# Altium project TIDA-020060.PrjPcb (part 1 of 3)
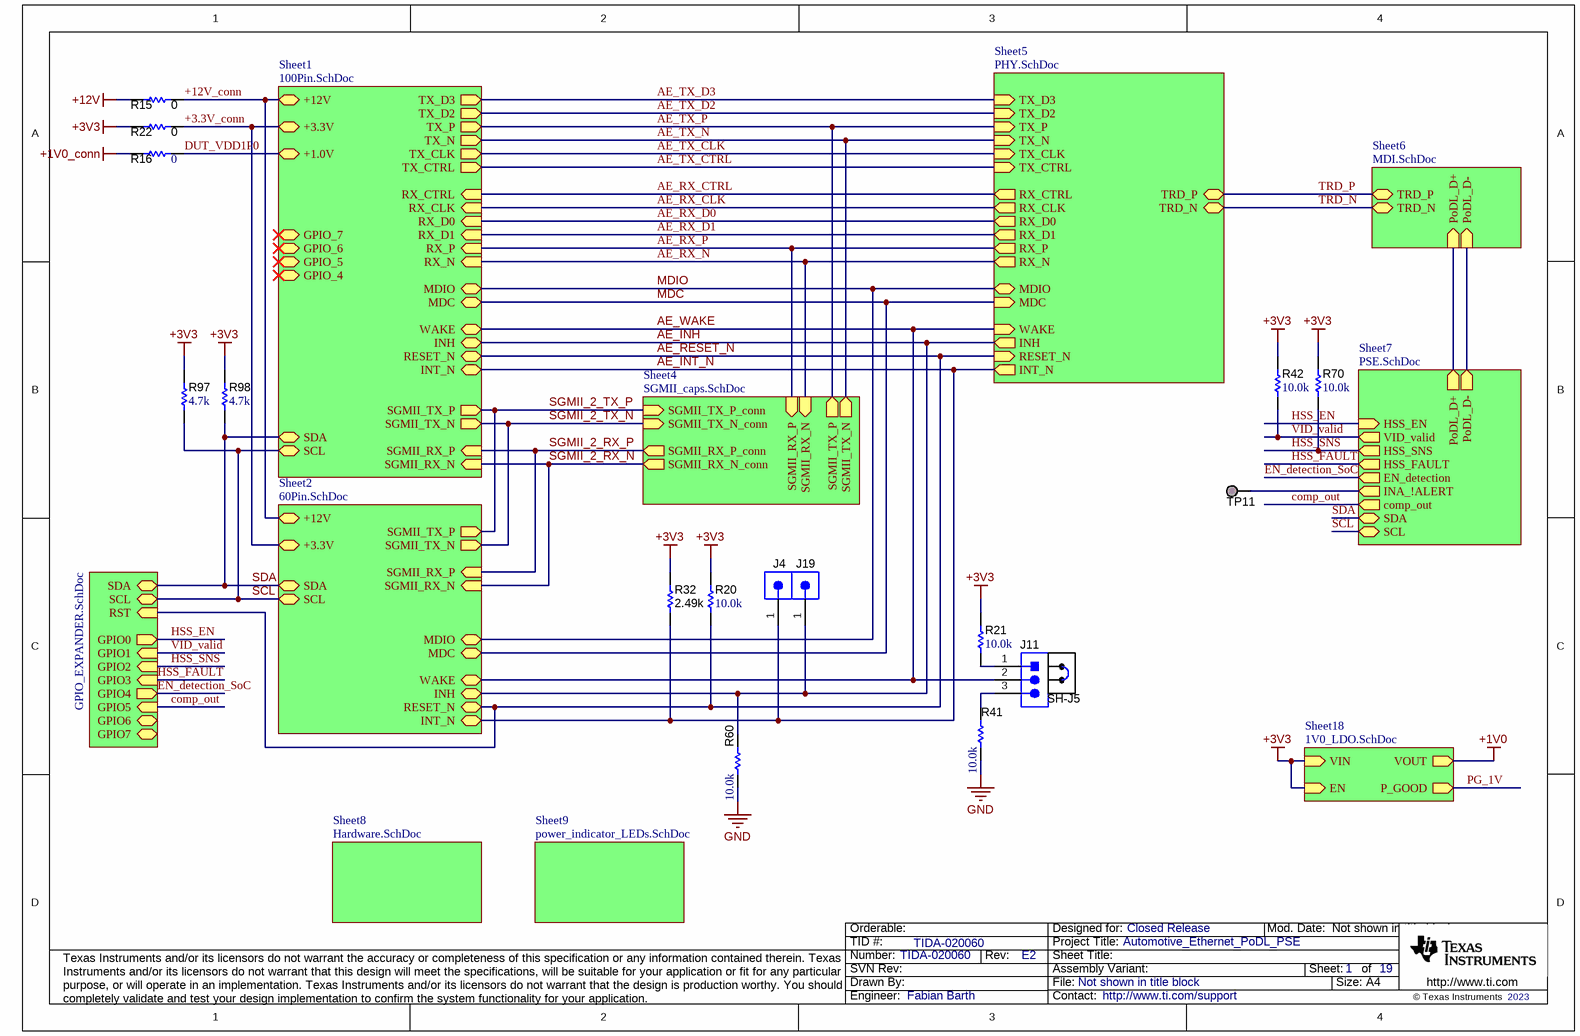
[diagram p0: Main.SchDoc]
CopyrightYear: 2023; PCB_Layout: Fabian Barth; PCB_Rev: E2; PRJ_Customer: Closed Release; PRJ_Engineer: Fabian Barth; PRJ_Number: TIDA-020060; PRJ_Title: Automotive_Ethernet_PoDL_PSE; SCH_Rev: E2; TechSupport: http://www.ti.com/support; TID: TIDA-020060
19 sheets, 281 parts. Net scope: hierarchical (ports join the sheet entries above them; power ports are global).
Board file: TIDA-020060.PcbDoc
Sheets:
  Main.SchDoc
    Sheet5 = PHY.SchDoc
      Sheet10 = Power_caps.SchDoc
      Sheet11 = PHY_LED.SchDoc
    Sheet6 = MDI.SchDoc
    Sheet8 = Hardware.SchDoc
    Sheet1 = 100Pin.SchDoc
    Sheet2 = 60Pin.SchDoc
      Sheet3 = Board_ID_EEPROM.SchDoc
    Sheet4 = SGMII_caps.SchDoc
    Sheet9 = power_indicator_LEDs.SchDoc
    Sheet18 = 1V0_LDO.SchDoc
    Sheet7 = PSE.SchDoc
      HSS = High_side_switch.SchDoc
      LM5158QRTERQ1 = PSE_BOOST.SchDoc
      Detections_sheet = Detection_PSE.SchDoc
      current_sense_sheet = INA237.SchDoc
    GPIO_expander = GPIO_EXPANDER.SchDoc
  Automotive_PoDL_PSE_Adapter_Hardware.SchDoc

## Sheet Main.SchDoc
size A4; Date: Not shown in title block; ApprovedBy: Not shown in title block; CheckedBy: Not shown in title block; Author: Not shown in title block; CompanyName: Not shown in title block; Engineer: Not shown in title block; Organization: Not shown in title block; Address1: Not shown in title block; Address2: Not shown in title block; Address3: Not shown in title block; Address4: Not shown in title block; DocumentNumber: 1; Revision: Use project parameter SCH_Rev; SheetNumber: 1; SheetTotal: 19; PageSetup: Record=PageOptions¦CenterHorizontal=True¦CenterVertical=True¦PrintScale=0.93¦XCorrection=1.00¦YCorrection=1.00¦PrintKind=0¦BorderSize=5000000¦LeftOffset=0¦BottomOffset=0¦Orientation=2¦PaperLength=1000¦PaperWidth=1000¦Scale=100¦PaperSource=15¦PrintQuality=600¦MediaType=1¦DitherType=10¦PaperKind=Letter¦PrintScaleMode=1

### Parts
J4  61300111121  [WURTH_61300111121]  (value not drawn)
J11  TSW-103-07-G-S  [TSW-103-07-G-S]  (value not drawn)
J19  61300111121  [WURTH_61300111121]  (value not drawn)
R15  ValueDisplayed: 0  [0603]  (hidden comment: RMCF0603ZT0R00)
R16  ValueDisplayed: 0  [0402]  (hidden comment: RK73Z1ETTP)
R20  ValueDisplayed: 10.0k  [0402]  (hidden comment: RMCF0402FT10K0)
R21  ValueDisplayed: 10.0k  [0402]  (hidden comment: RMCF0402FT10K0)
R22  ValueDisplayed: 0  [0603]  (hidden comment: RMCF0603ZT0R00)
R32  ValueDisplayed: 2.49k  [0603]  (hidden comment: CRCW06032K49FKEA)
R41  ValueDisplayed: 10.0k  [0402]  (hidden comment: RMCF0402FT10K0)
R42  ValueDisplayed: 10.0k  [0603]  (hidden comment: RT0603DRE0710KL)
R60  ValueDisplayed: 10.0k  [0402]  (hidden comment: RMCF0402FT10K0)
R70  ValueDisplayed: 10.0k  [0402]  (hidden comment: RMCF0402FT10K0)
R97  ValueDisplayed: 4.7k  [0402S]  (hidden comment: CRCW04024K70JNED)
R98  ValueDisplayed: 4.7k  [0402S]  (hidden comment: CRCW04024K70JNED)
SH-J5  SPC02SYAN  [SPC02SYAN]  (value not drawn)
TP11  TP_SM_1MM  [TP_SM_1MM]  (value not drawn)  (no BOM)

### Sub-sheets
GPIO_expander = GPIO_EXPANDER.SchDoc: RST (in), SCL (bidir), SDA (bidir), GPIO0 (out), GPIO1 (in), GPIO2 (in), GPIO3 (in), GPIO4 (out), GPIO5 (in), GPIO6 (bidir), GPIO7 (bidir)
Sheet1 = 100Pin.SchDoc: +12V (bidir), +3.3V (bidir), +1.0V (bidir), SGMII_TX_P (out), SGMII_TX_N (out), SGMII_RX_P (in), SGMII_RX_N (in), INT_N (bidir), RESET_N (bidir), INH (bidir), WAKE (bidir), MDIO (bidir), MDC (bidir), TX_D3 (out), TX_D2 (out), TX_P (out), TX_N (out), TX_CLK (out), TX_CTRL (out), RX_CTRL (in), RX_CLK (in), RX_D0 (in), RX_D1 (in), RX_P (in), RX_N (in), SDA (bidir), SCL (bidir), GPIO_7 (bidir), GPIO_6 (bidir), GPIO_5 (bidir), GPIO_4 (bidir)
Sheet2 = 60Pin.SchDoc: +12V (bidir), +3.3V (bidir), SDA (bidir), SCL (bidir), WAKE (bidir), INH (bidir), RESET_N (bidir), MDIO (bidir), MDC (bidir), SGMII_RX_N (in), SGMII_RX_P (in), SGMII_TX_N (out), SGMII_TX_P (out), INT_N (bidir)
Sheet4 = SGMII_caps.SchDoc: SGMII_RX_P (in), SGMII_RX_N (in), SGMII_TX_P (out), SGMII_TX_N (out), SGMII_RX_P_conn (out), SGMII_RX_N_conn (out), SGMII_TX_P_conn (in), SGMII_TX_N_conn (in)
Sheet5 = PHY.SchDoc: TX_D3 (in), TX_D2 (in), TX_P (in), TX_N (in), TX_CLK (in), TX_CTRL (in), RX_CTRL (out), RX_CLK (out), RX_D0 (out), RX_D1 (out), RX_P (out), RX_N (out), MDIO (bidir), MDC (in), TRD_P (bidir), TRD_N (bidir), WAKE (in), RESET_N (in), INT_N (out), INH (out)
Sheet6 = MDI.SchDoc: TRD_P (bidir), TRD_N (bidir), PoDL_D+ (in), PoDL_D- (in)
Sheet7 = PSE.SchDoc: PoDL_D+ (out), PoDL_D- (out), HSS_EN (in), VID_valid (out), HSS_SNS (out), HSS_FAULT (out), EN_detection (out), INA_!ALERT (out), SDA (bidir), SCL (bidir), comp_out (out)
Sheet8 = Hardware.SchDoc: no entries
Sheet9 = power_indicator_LEDs.SchDoc: no entries
Sheet18 = 1V0_LDO.SchDoc: EN (in), VIN (in), P_GOOD (out), VOUT (out)

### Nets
+1V0_conn: R16.2
+3V3: R20.2 R21.2 R22.1 R32.1 R42.2 R70.2 R97.2 R98.2 ; sheet Sheet18/EN, sheet Sheet18/VIN
+12V: R15.1
GND: R41.2 R60.2
!ALERT: TP11.1 ; sheet Sheet7/INA_!ALERT
+3.3V_conn: R22.2 ; sheet Sheet1/+3.3V, sheet Sheet2/+3.3V
+12V_conn: R15.2 ; sheet Sheet1/+12V, sheet Sheet2/+12V
AE_INH: J19.1 R60.1 ; sheet Sheet5/INH, sheet Sheet1/INH, sheet Sheet2/INH
AE_INT_N: J4.1 R32.2 ; sheet Sheet5/INT_N, sheet Sheet1/INT_N, sheet Sheet2/INT_N
AE_RESET_N: R20.1 ; sheet Sheet5/RESET_N, sheet Sheet1/RESET_N, sheet Sheet2/RESET_N, sheet GPIO_expander/RST
AE_RX_CLK: sheet Sheet5/RX_CLK, sheet Sheet1/RX_CLK
AE_RX_CTRL: sheet Sheet5/RX_CTRL, sheet Sheet1/RX_CTRL
AE_RX_D0: sheet Sheet5/RX_D0, sheet Sheet1/RX_D0
AE_RX_D1: sheet Sheet5/RX_D1, sheet Sheet1/RX_D1
AE_RX_N: sheet Sheet5/RX_N, sheet Sheet1/RX_N, sheet Sheet4/SGMII_RX_N
AE_RX_P: sheet Sheet5/RX_P, sheet Sheet1/RX_P, sheet Sheet4/SGMII_RX_P
AE_TX_CLK: sheet Sheet5/TX_CLK, sheet Sheet1/TX_CLK
AE_TX_CTRL: sheet Sheet5/TX_CTRL, sheet Sheet1/TX_CTRL
AE_TX_D2: sheet Sheet5/TX_D2, sheet Sheet1/TX_D2
AE_TX_D3: sheet Sheet5/TX_D3, sheet Sheet1/TX_D3
AE_TX_N: sheet Sheet5/TX_N, sheet Sheet1/TX_N, sheet Sheet4/SGMII_TX_N
AE_TX_P: sheet Sheet5/TX_P, sheet Sheet1/TX_P, sheet Sheet4/SGMII_TX_P
AE_WAKE: J11.2 ; sheet Sheet5/WAKE, sheet Sheet1/WAKE, sheet Sheet2/WAKE
comp_out: sheet Sheet7/comp_out, sheet GPIO_expander/GPIO5
DUT_VDD1P0: R16.1 ; sheet Sheet1/+1.0V
EN_detection_SoC: sheet Sheet7/EN_detection, sheet GPIO_expander/GPIO4
HSS_EN: sheet Sheet7/HSS_EN, sheet GPIO_expander/GPIO0
HSS_FAULT: sheet Sheet7/HSS_FAULT, sheet GPIO_expander/GPIO3
HSS_SNS: R70.1 ; sheet Sheet7/HSS_SNS, sheet GPIO_expander/GPIO2
MDC: sheet Sheet5/MDC, sheet Sheet1/MDC, sheet Sheet2/MDC
MDIO: sheet Sheet5/MDIO, sheet Sheet1/MDIO, sheet Sheet2/MDIO
PoDL_D+: sheet Sheet6/PoDL_D+, sheet Sheet7/PoDL_D+
PoDL_D-: sheet Sheet6/PoDL_D-, sheet Sheet7/PoDL_D-
SCL: R97.1 ; sheet Sheet1/SCL, sheet Sheet2/SCL, sheet Sheet7/SCL, sheet GPIO_expander/SCL
SDA: R98.1 ; sheet Sheet1/SDA, sheet Sheet2/SDA, sheet Sheet7/SDA, sheet GPIO_expander/SDA
SGMII_2_RX_N: sheet Sheet1/SGMII_RX_N, sheet Sheet2/SGMII_RX_N, sheet Sheet4/SGMII_RX_N_conn
SGMII_2_RX_P: sheet Sheet1/SGMII_RX_P, sheet Sheet2/SGMII_RX_P, sheet Sheet4/SGMII_RX_P_conn
SGMII_2_TX_N: sheet Sheet1/SGMII_TX_N, sheet Sheet2/SGMII_TX_N, sheet Sheet4/SGMII_TX_N_conn
SGMII_2_TX_P: sheet Sheet1/SGMII_TX_P, sheet Sheet2/SGMII_TX_P, sheet Sheet4/SGMII_TX_P_conn
TRD_N: sheet Sheet5/TRD_N, sheet Sheet6/TRD_N
TRD_P: sheet Sheet5/TRD_P, sheet Sheet6/TRD_P
VID_valid: R42.1 ; sheet Sheet7/VID_valid, sheet GPIO_expander/GPIO1  [project net Q]
NetJ11_1: J11.1 R21.1
NetJ11_3: J11.3 R41.1

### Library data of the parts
J4 J19 = CMP-0054792-1: Header, 2.54 mm, 1x1, Gold, TH; Manufacturer: Wurth Elektronik; CNHeader: TRUE; CT: FALSE
J11 = CMP-0075407-2: Header, 100mil, 3x1, Gold, TH; Manufacturer: Samtec; Pitch_mm: 2.54; Cert_VDE: N; Gender: Male; Cert_CSA: Y; Voltage_V: 550V; Green_REACh: Passed; Current_A: 6.3A; Green_Lifecycle: Active; Row_Count: 1
R15 R22 = CMP-0023343-3: RES, 0, 1%, 0.1 W, AEC-Q200 Grade 0, 0603; Manufacturer: Stackpole Electronics Inc; Power_W: 100mW; TempCo: ppm/C; U/M: EA; Value: 0; SizeX_mm: 1.6; SizeY_mm: 0.8; SizeZ_mm: 1; Value2: 0.1W; SizeArea_mm2: 1.28; AEC Qualified: Y; AEC Category: Q200
R16 = CMP-0027007-2: RES, 0, 5%, 0.063 W, AEC-Q200 Grade 0, 0402; Manufacturer: KOA Speer; Power_W: 63mW; TempCo: ppm/C; Value_Code: 0000; Value: 0; EIA_Code: E24; SizeX_mm: 1; SizeY_mm: 0.5; SizeZ_mm: 0.6; Value2: 0.063W; AEC Qualified: Y; AEC Category: Q200; U/M: EA
R20 R21 R70 = CMP-0026754-1: RES, 10.0 k, 1%, 0.063 W, AEC-Q200 Grade 0, 0402; Manufacturer: Stackpole Electronics Inc; Power_W: 63mW; TempCo: 100 ppm/C; Value_Code: 10k0; U/M: EA; Value: 10.0k; EIA_Code: E96; Res_ohm: 10k; SizeX_mm: 1; SizeY_mm: 0.5; SizeZ_mm: 0.6; Value2: 0.063W; AEC Qualified: Y; VDC_V: 50V; AEC Grade: 0; AEC Category: Q200
R32 = CMP-0022277-4: RES, 2.49 k, 1%, 0.1 W, AEC-Q200 Grade 0, 0603; Manufacturer: Vishay-Dale; Power_W: 100mW; TempCo: 100 ppm/C; Value_Code: 2k49; Value: 2.49k; EIA_Code: E96; SizeX_mm: 1.6; SizeY_mm: 0.8; SizeZ_mm: 1; Value2: 0.1W; SizeArea_mm2: 1.28; AEC Qualified: Y; VDC_V: 75V; AEC Category: Q200; AEC Grade: 0
R41 R60 = CMP-0026754-1: RES, 10.0 k, 1%, 0.063 W, AEC-Q200 Grade 0, 0402; Manufacturer: Stackpole Electronics Inc; Power_W: 63mW; TempCo: 100 ppm/C; Value_Code: 10k0; Value: 10.0k; EIA_Code: E96; Res_ohm: 10k; SizeX_mm: 1; SizeY_mm: 0.5; SizeZ_mm: 0.6; Value2: 0.063W; AEC Qualified: Y; VDC_V: 50V; AEC Category: Q200; AEC Grade: 0; U/M: EA
R42 = CMP-0024586-3: RES, 10.0 k, 0.5%, 0.1 W, 0603; Manufacturer: Yageo America; Power_W: 100mW; TempCo: 50 ppm/C; Value_Code: 10k0; U/M: EA; Value: 10.0k; EIA_Code: E192; Res_ohm: 10k; SizeX_mm: 1.6; SizeY_mm: 0.8; SizeZ_mm: 1; Value2: 0.1W; SizeArea_mm2: 1.28; VDC_V: 75V; AEC Category: Q200
R97 R98 = CMP-0026938-5: RES, 4.7 k, 5%, 0.063 W, AEC-Q200 Grade 0, 0402; Manufacturer: Vishay-Dale; Power_W: 63mW; TempCo: 200 ppm/C; Value_Code: 4k70; Value: 4.7k; EIA_Code: E24; SizeX_mm: 1; SizeY_mm: 0.5; SizeZ_mm: 0.6; Value2: 0.063W; AEC Qualified: Y; VDC_V: 50V; AEC Grade: 0; AEC Category: Q200
SH-J5 = CMP-0003642-1: Shunt, 100mil, Flash Gold, Black; Manufacturer: Sullins Connector Solutions; Value: 1x2; Note: You can "mate" this to a header by matching the designator.  i.e. use SH-J3 for header J3
TP11 = CMP-0003825-1: 1mm Test Point, SMT; Manufacturer: Any

## Sheet PHY.SchDoc
size A4; Date: Not shown in title block; ApprovedBy: Not shown in title block; CheckedBy: Not shown in title block; Author: Not shown in title block; CompanyName: Not shown in title block; Engineer: Not shown in title block; Organization: Not shown in title block; Address1: Not shown in title block; Address2: Not shown in title block; Address3: Not shown in title block; Address4: Not shown in title block; DocumentNumber: 6; Revision: Use project parameter SCH_Rev; SheetNumber: 6; SheetTotal: 19; PageSetup: Record=PageOptions¦CenterHorizontal=True¦CenterVertical=True¦PrintScale=0.93¦XCorrection=1.00¦YCorrection=1.00¦PrintKind=0¦BorderSize=5000000¦LeftOffset=0¦BottomOffset=0¦Orientation=2¦PaperLength=1000¦PaperWidth=1000¦Scale=100¦PaperSource=15¦PrintQuality=600¦MediaType=1¦DitherType=10¦PaperKind=Letter¦PrintScaleMode=1
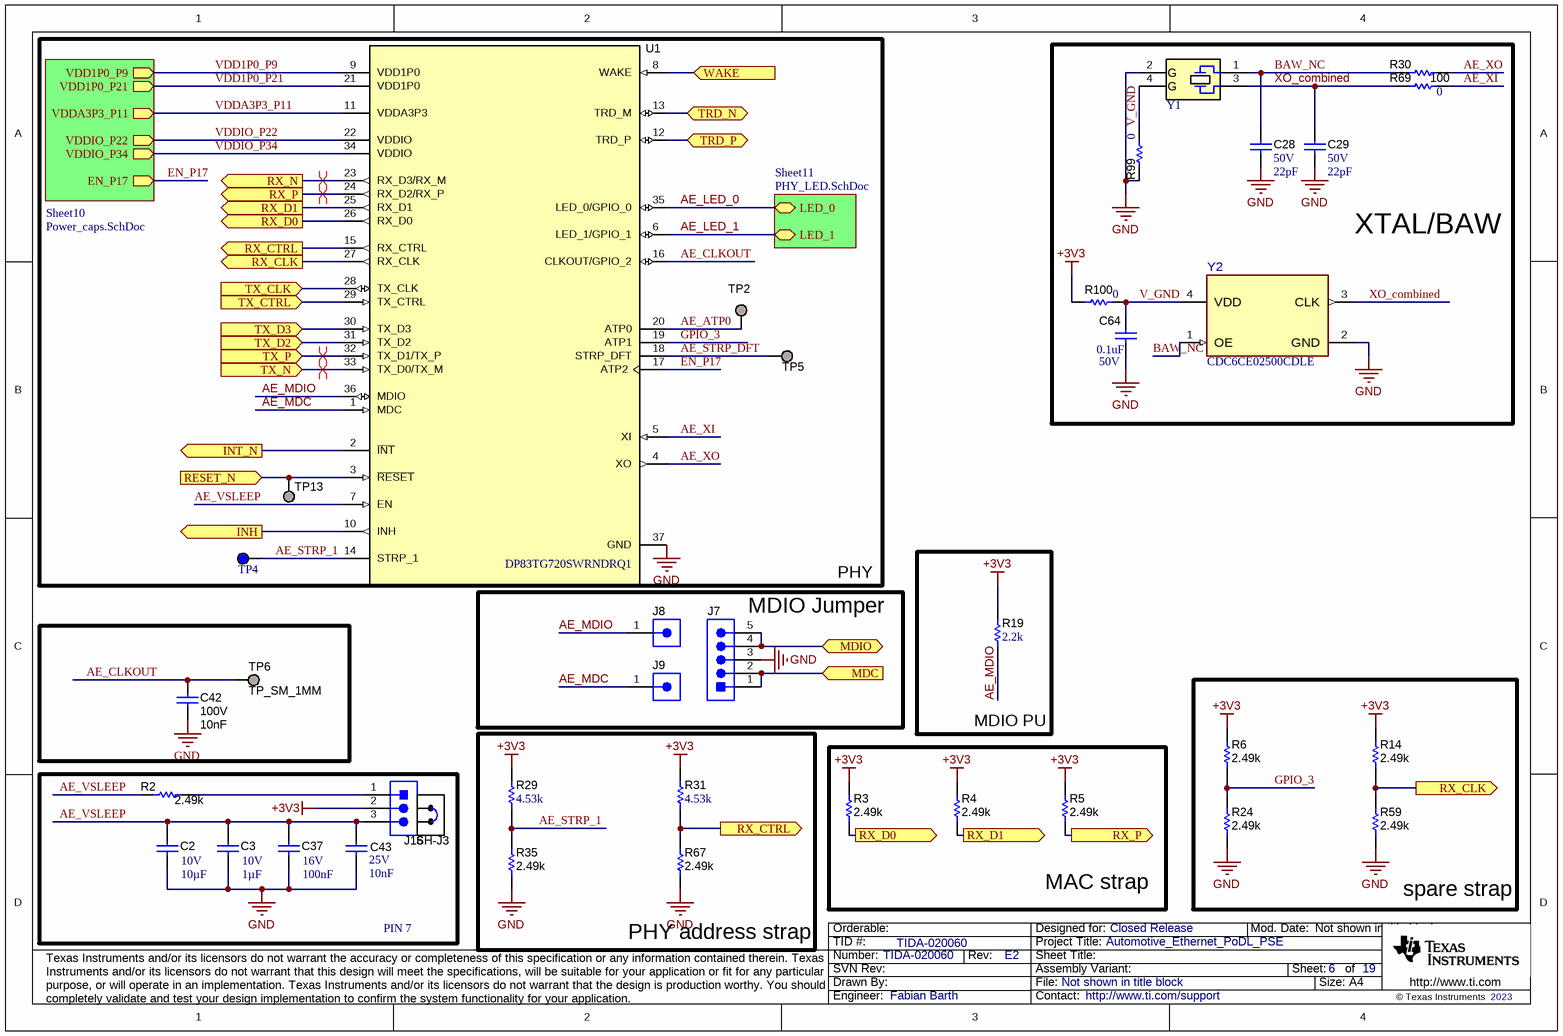
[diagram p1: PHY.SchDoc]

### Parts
C2  VDC_V: 10V  Cap_F: 10µF  [0402S]  (hidden comment: GRM155R61A106ME11D)
C3  Cap_F: 1µF  VDC_V: 10V  [0402S]  (hidden comment: GRT155C71A105KE13D)
C28  VDC_V: 50V  ValueDisplayed: 22pF  [0603]  (hidden comment: CGA3E2C0G1H220J080AA)
C29  VDC_V: 50V  ValueDisplayed: 22pF  [0603]  (hidden comment: CGA3E2C0G1H220J080AA)
C37  Cap_F: 100nF  VDC_V: 16V  [0402S]  (hidden comment: C0402C104K4RACAUTO)
C42  VDC_V: 100V  Cap_F: 10nF  [0603]  (hidden comment: GCM188R72A103KA37J)
C43  VDC_V: 25V  Cap_F: 10nF  [0402S]  (hidden comment: GRM155R71E103KA01D)
C64  ValueDisplayed: 0.1uF  VDC_V: 50V  [0402]  (hidden comment: C1005X5R1H104K050BB)
J7  TSW-105-07-G-S  [TSW-105-07-X-S]  (value not drawn)
J8  61300111121  [WURTH_61300111121]  (value not drawn)
J9  61300111121  [WURTH_61300111121]  (value not drawn)
J16  TSW-103-07-G-S  [TSW-103-07-X-S]  (value not drawn)
R2  ValueDisplayed: 2.49k  [0603]  (hidden comment: CRCW06032K49FKEA)
R3  ValueDisplayed: 2.49k  [0603]  (hidden comment: CRCW06032K49FKEA)
R4  ValueDisplayed: 2.49k  [0603]  (hidden comment: CRCW06032K49FKEA)
R5  ValueDisplayed: 2.49k  [0603]  (hidden comment: CRCW06032K49FKEA)
R6  ValueDisplayed: 2.49k  [0603]  (hidden comment: CRCW06032K49FKEA)
R14  ValueDisplayed: 2.49k  [0603]  (hidden comment: CRCW06032K49FKEA)
R19  ValueDisplayed: 2.2k  [0402]  (hidden comment: CRCW04022K20JNED)
R24  ValueDisplayed: 2.49k  [0603]  (hidden comment: CRCW06032K49FKEA)
R29  ValueDisplayed: 4.53k  [0603]  (hidden comment: CRCW06034K53FKEA)
R30  ValueDisplayed: 100  [0402]  (hidden comment: CRCW0402100RFKED)
R31  ValueDisplayed: 4.53k  [0603]  (hidden comment: CRCW06034K53FKEA)
R35  ValueDisplayed: 2.49k  [0603]  (hidden comment: CRCW06032K49FKEA)
R59  ValueDisplayed: 2.49k  [0603]  (hidden comment: CRCW06032K49FKEA)
R67  ValueDisplayed: 2.49k  [0603]  (hidden comment: CRCW06032K49FKEA)
R69  ValueDisplayed: 0  [0402]  (hidden comment: CRCW04020000Z0EDHP)
R99  ValueDisplayed: 0  [0402]  (hidden comment: CRCW04020000Z0EDHP)
R100  ValueDisplayed: 0  [0402]  (hidden comment: CRCW04020000Z0EDHP)
SH-J3  SPC02SYAN  [SPC02SYAN]  (value not drawn)
TP2  TP_SM_1MM  [TP_SM_1MM]  (value not drawn)  (no BOM)
TP4  5127  [Keystone5127]  (value not drawn)
TP5  TP_SM_1MM  [TP_SM_1MM]  (value not drawn)  (no BOM)
TP6  TP_SM_1MM  [TP_SM_1MM]  (no BOM)
TP13  TP_SM_1MM  [TP_SM_1MM]  (value not drawn)  (no BOM)
U1  DP83TG720SWRNDRQ1  [RND0036A]
Y1  ABM8AIG-25.000MHZ-12-2Z-T3  [Abracon_ABM8AIG]  (value not drawn)
Y2  CDC6CE02500CDLE  [DLE0004A-MFG]

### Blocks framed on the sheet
PHY: TP2 TP4 TP5 TP13 U1
XTAL/BAW: C28 C29 C64 R30 R69 R99 R100 Y1 Y2
MDIO PU: R19
MDIO Jumper: J7-J9
PHY address strap: R29 R31 R35 R67
spare strap: R6 R14 R24 R59
PIN 7: C2 C3 C37 C43 J16 R2 SH-J3
MAC strap: R3-R5

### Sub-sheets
Sheet10 = Power_caps.SchDoc: VDD1P0_P9 (out), VDD1P0_P21 (out), VDDA3P3_P11 (out), VDDIO_P22 (out), VDDIO_P34 (out), EN_P17 (out)
Sheet11 = PHY_LED.SchDoc: LED_0 (bidir), LED_1 (bidir)

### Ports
INH (out), INT_N (out), MDC (in), MDIO (bidir), RESET_N (in), RX_CLK (out), RX_CTRL (out), RX_D0 (out), RX_D1 (out), RX_N (out), RX_P (out), TRD_N (bidir), TRD_P (bidir), TX_CLK (in), TX_CTRL (in), TX_D2 (in), TX_D3 (in), TX_N (in), TX_P (in), WAKE (in)

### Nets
+3V3: J16.2 R3.1 R4.1 R5.1 R6.1 R14.1 R19.2 R29.1 R31.2 R100.1
GND: C2.2 C3.2 C28.2 C29.2 C37.2 C42.2 C43.1 C64.1 J7.3 R24.1 R35.1 R59.1 R67.1 R99.1 U1.37(GND) Y1.2(GND) Y2.2(GND)
AE_ATP0: TP2.1 U1.20(ATP0)
AE_CLKOUT: C42.1 TP6.1 U1.16(CLKOUT/GPIO_2)
AE_INH: U1.10(INH) ; port INH
AE_INT_N: U1.2(~{INT}) ; port INT_N
AE_LED_0: U1.35(LED_0/GPIO_0) ; sheet Sheet11/LED_0
AE_LED_1: U1.6(LED_1/GPIO_1) ; sheet Sheet11/LED_1
AE_MDC: J9.1 U1.1(MDC)
AE_MDIO: J8.1 R19.1 U1.36(MDIO)
AE_RESET_N: TP13.1 U1.3(~{RESET}) ; port RESET_N
AE_RX_CLK: R14.2 R59.2 U1.27(RX_CLK) ; port RX_CLK
AE_RX_CTRL: R31.1 R67.2 U1.15(RX_CTRL) ; port RX_CTRL
AE_RX_D0: R3.2 U1.26(RX_D0) ; port RX_D0
AE_RX_D1: R4.2 U1.25(RX_D1) ; port RX_D1
AE_RX_N: U1.23(RX_D3/RX_M) ; port RX_N
AE_RX_P: R5.2 U1.24(RX_D2/RX_P) ; port RX_P
AE_STRP_1: R29.2 R35.2 TP4.1 U1.14(STRP_1)
AE_STRP_DFT: TP5.1 U1.18(STRP_DFT)
AE_TX_CLK: U1.28(TX_CLK) ; port TX_CLK
AE_TX_CTRL: U1.29(TX_CTRL) ; port TX_CTRL
AE_TX_D2: U1.31(TX_D2) ; port TX_D2
AE_TX_D3: U1.30(TX_D3) ; port TX_D3
AE_TX_N: U1.33(TX_D0/TX_M) ; port TX_N
AE_TX_P: U1.32(TX_D1/TX_P) ; port TX_P
AE_VSLEEP: C2.1 C3.1 C37.1 C43.2 J16.3 R2.1 U1.7(EN)
AE_WAKE: U1.8(WAKE) ; port WAKE
AE_XI: R69.1 U1.5(XI)
AE_XO: R30.1 U1.4(XO)
BAW_NC: C28.1 R30.2 Y1.1 Y2.1(OE)
EN_P17: U1.17(ATP2) ; sheet Sheet10/EN_P17
GPIO_3: R6.2 R24.2 U1.19(ATP1)
MDC: J7.1 J7.2 ; port MDC
MDIO: J7.4 J7.5 ; port MDIO
TRD_N: U1.13(TRD_M) ; port TRD_N
TRD_P: U1.12(TRD_P) ; port TRD_P
V_GND: C64.2 R99.2 R100.2 Y1.4(GND) Y2.4(VDD)
VDD1P0_P9: U1.9(VDD1P0) ; sheet Sheet10/VDD1P0_P9
VDD1P0_P21: U1.21(VDD1P0) ; sheet Sheet10/VDD1P0_P21
VDDA3P3_P11: U1.11(VDDA3P3) ; sheet Sheet10/VDDA3P3_P11
VDDIO_P22: U1.22(VDDIO) ; sheet Sheet10/VDDIO_P22
VDDIO_P34: U1.34(VDDIO) ; sheet Sheet10/VDDIO_P34
XO_combined: C29.1 R69.2 Y1.3 Y2.3(CLK)
NetJ16_1: J16.1 R2.2

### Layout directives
differential pair: AE_RX_N, AE_RX_P, AE_TX_N, AE_TX_P

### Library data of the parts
C2 = CMP-0006564-3: CAP, CERM, 10 uF, 10 V, +/- 20%, X5R, 0402; Manufacturer: MuRata; SizeY_mm: 0.5; SizeAreaWB_mm2: 3; ValueDisplayed: 10uF; SizeX_mm: 1; Value1: Unknown; Cap_Case: 0402; Value: 10uF; U/M: EA; SizeZ_mm: 0.6; TaMax_C: 85°C; AEC Category: Q200; Polarized: N; TaMin_C: -55°C
C3 = CMP-0085818-1: CAP, CERM, 1 µF, 10 V,+/- 10%, X7S, AEC-Q200 Grade 1, 0402; Manufacturer: MuRata; SizeArea_mm2: 0.5; Cap_Case: 0402; AEC Category: Q200; AEC Qualified: Y; TaMax_C: 125°C; SizeZ_mm: 0.6; SizeX_mm: 1; Polarized: N; Value: 1uF; SizeAreaWB_mm2: 3; TaMin_C: -55°C; U/M: EA
C28 C29 = CMP-0007071-4: CAP, CERM, 22 pF, 50 V, +/- 5%, C0G/NP0, AEC-Q200 Grade 1, 0603; Manufacturer: TDK; TaMin_C: -55°C; Polarized: N; SizeAreaWB_mm2: 4.68; Value1: Unknown; U/M: EA; Value: 22pF; TaMax_C: 125°C; SizeZ_mm: 1; SizeX_mm: 1.6; SizeY_mm: 0.8; SizeArea_mm2: 1.28; AEC Qualified: Y; AEC Category: Q200
C37 = CMP-0006237-2: CAP, CERM, 0.1 uF, 16 V, +/- 10%, X7R, AEC-Q200 Grade 1, 0402; Manufacturer: Kemet; SizeAreaWB_mm2: 3; SizeArea_mm2: 0.5; AEC Qualified: Y; AEC Category: Q200; Value: 0.1uF; TaMax_C: 125°C; SizeZ_mm: 0.6; AEC Grade: 1; Polarized: N; TaMin_C: -55°C; U/M: EA; Cap_Case: 0402; Value1: Unknown
C42 = CMP-0084773-1: CAP, CERM, 0.01 µF, 100 V,+/- 10%, X7R, AEC-Q200 Grade 1, 0603; Manufacturer: MuRata; AEC Qualified: Y; SizeX_mm: 1.6; TaMin_C: -55°C; SizeArea_mm2: 1.28; AEC Category: Q200; ValueDisplayed: 0.01µF; SizeZ_mm: 1; Value: 0.01uF; Polarized: N; SizeAreaWB_mm2: 4.68; TaMax_C: 125°C; SizeY_mm: 0.8; U/M: EA
C43 = CMP-0006658-2: CAP, CERM, 0.01 uF, 25 V, +/- 10%, X7R, 0402; Manufacturer: MuRata; Value1: Unknown; Cap_Case: 0402; SizeX_mm: 1; TaMin_C: -55°C; SizeArea_mm2: 0.5; AEC Category: Q200; ValueDisplayed: 0.01uF; SizeZ_mm: 0.6; Value: 0.01uF; Polarized: N; SizeAreaWB_mm2: 3; TaMax_C: 125°C; U/M: EA
C64 = CMP-0006279-2: CAP, CERM, 0.1 uF, 50 V, +/- 10%, X5R, 0402; Manufacturer: TDK; Polarized: N; Value: 0.1uF; U/M: EA; Cap_F: 100nF; ESR_ohm: 39.064m; Value1: 0.039064 ohm; IRMS_A: 814.669mA; TaMin_C: -55°C; TaMax_C: 85°C; SizeArea_mm2: 0.5; SizeAreaWB_mm2: 3; SizeX_mm: 1; SizeZ_mm: 0.6; AEC Category: Q200
J7 = CMP-0075411-1: Header, 100mil, 5x1, Gold, TH; Manufacturer: Samtec; Pitch_mm: 2.54; Cert_VDE: N; Gender: Male; Cert_CSA: Y; Voltage_V: 550V; Green_REACh: Passed; Current_A: 6.3A; Green_Lifecycle: Active; Row_Count: 1; CT: False; CNHeader: True
J8 J9 = CMP-0054792-1: as J4 on sheet Main
J16 = CMP-0075407-1: Header, 100mil, 3x1, Gold, TH; Manufacturer: Samtec; Pitch_mm: 2.54; Cert_VDE: N; Gender: Male; Cert_CSA: Y; Voltage_V: 550V; Green_REACh: Passed; Current_A: 6.3A; CT: False; Green_Lifecycle: Active; Row_Count: 1; CNHeader: True
R2-R6 R14 R24 R35 R59 R67 = CMP-0022277-4: as R32 on sheet Main
R19 = CMP-0026890-5: RES, 2.2 k, 5%, 0.063 W, AEC-Q200 Grade 0, 0402; Manufacturer: Vishay-Dale; Power_W: 63mW; TempCo: 200 ppm/C; Value_Code: 2k20; Value: 2.2k; EIA_Code: E24; SizeX_mm: 1; SizeY_mm: 0.5; SizeZ_mm: 0.6; Value2: 0.063W; AEC Qualified: Y; VDC_V: 50V; AEC Grade: 0; AEC Category: Q200
R29 R31 = CMP-0022454-4: RES, 4.53 k, 1%, 0.1 W, AEC-Q200 Grade 0, 0603; Manufacturer: Vishay-Dale; Power_W: 100mW; TempCo: 100 ppm/C; Value_Code: 4k53; Value: 4.53k; EIA_Code: E96; SizeX_mm: 1.6; SizeY_mm: 0.8; SizeZ_mm: 1; Value2: 0.1W; SizeArea_mm2: 1.28; AEC Qualified: Y; VDC_V: 75V; AEC Category: Q200; AEC Grade: 0
R30 = CMP-0025951-1: RES, 100, 1%, 0.063 W, 0402; Manufacturer: Vishay-Dale; Power_W: 63mW; TempCo: 100 ppm/C; Value_Code: 100R; U/M: EA; Value: 100; EIA_Code: E96; SizeX_mm: 1; SizeY_mm: 0.5; SizeZ_mm: 0.6; Value2: 0.063W; VDC_V: 50V; AEC Category: Q200
R69 = CMP-0081856-1: RES, 0, 0%, 0.2 W, AEC-Q200 Grade 0, 0402; Manufacturer: Vishay-Dale; Power_W: 200mW; Value: 0; SizeX_mm: 1; SizeY_mm: 0.5; SizeZ_mm: 0.6; Value2: 0.2W; AEC Qualified: Y; VDC_V: 50V; AEC Category: Q200; SizeAreaWB_mm2: 3
R99 R100 = CMP-0081856-1: RES, 0, 0%, 0.2 W, AEC-Q200 Grade 0, 0402; Manufacturer: Vishay-Dale; Power_W: 200mW; Value: 0; SizeX_mm: 1; SizeY_mm: 0.5; SizeZ_mm: 0.6; Value2: 0.2W; AEC Qualified: Y; AEC Category: Q200; VDC_V: 50V; SizeAreaWB_mm2: 3
SH-J3 = CMP-0003642-1: as SH-J5 on sheet Main
TP2 TP5 TP6 TP13 = CMP-0003825-1: 1mm Test Point, SMT; Manufacturer: Any
TP4 = CMP-0055156-1: Test Point, Multipurpose, Blue, TH; Manufacturer: Keystone; CNHeader: FALSE; Green_Lifecycle: Active; Green_REACh: Passed; ContactFinish: Silver; CT: TRUE
U1 = CMP-0085268-1: Low Power Auto PHY 1000BASE-T1 Automotive Ethernet Physical Layer Transceiver, RND0036A (VQFNP-36); Manufacturer: Texas Instruments; Alternate PartNumber: DP83TG720SWRNDTQ1; SizeZ_mm: 0.9; AEC Qualified: Y; SizeY_mm: 6; SizeAreaWB_mm2: 64; SizeArea_mm2: 36; AEC Category: Q200; CompType: IC
Y1 = CMP-0004682-5: Crystal, 25 MHz, 12pF, AEC-Q200 Grade 1, SMD; Manufacturer: Abracon Corporation; TaMin_C: -40°C; Frequency Stability: 50 ppm; Frequency_Fixed: 25MHz; TaMax_C: 125°C; SizeAreaWB_mm2: 14.7; SizeArea_mm2: 8; SizeX_mm: 2.5; SizeY_mm: 3.2; SizeZ_mm: 0.8; AEC Category: Q200; AEC Grade: 1; AEC Qualified: Y
Y2 = CMP-0001498-1: Low Jitter, Low Power, LVCMOS Output, BAW Oscillator; Manufacturer: Texas Instruments; Min Supply Voltage: 1.62V; Frequency Stability: 20ppm; SizeZ_mm: 1mm; Standoff Height: 0mm; Max Supply Voltage: 3.63V; Frequency_Fixed: 25MHz; Max Supply Current: 5mA; AEC Qualified: Yes; AEC Grade: Grade 1

## Sheet Power_caps.SchDoc
size A4; Date: Not shown in title block; ApprovedBy: Not shown in title block; CheckedBy: Not shown in title block; Author: Not shown in title block; CompanyName: Not shown in title block; Engineer: Not shown in title block; Organization: Not shown in title block; Address1: Not shown in title block; Address2: Not shown in title block; Address3: Not shown in title block; Address4: Not shown in title block; DocumentNumber: 7; Revision: Use project parameter SCH_Rev; SheetNumber: 7; SheetTotal: 19; PageSetup: Record=PageOptions¦CenterHorizontal=True¦CenterVertical=True¦PrintScale=0.93¦XCorrection=1.00¦YCorrection=1.00¦PrintKind=0¦BorderSize=5000000¦LeftOffset=0¦BottomOffset=0¦Orientation=2¦PaperLength=1000¦PaperWidth=1000¦Scale=100¦PaperSource=15¦PrintQuality=600¦MediaType=1¦DitherType=10¦PaperKind=Letter¦PrintScaleMode=1
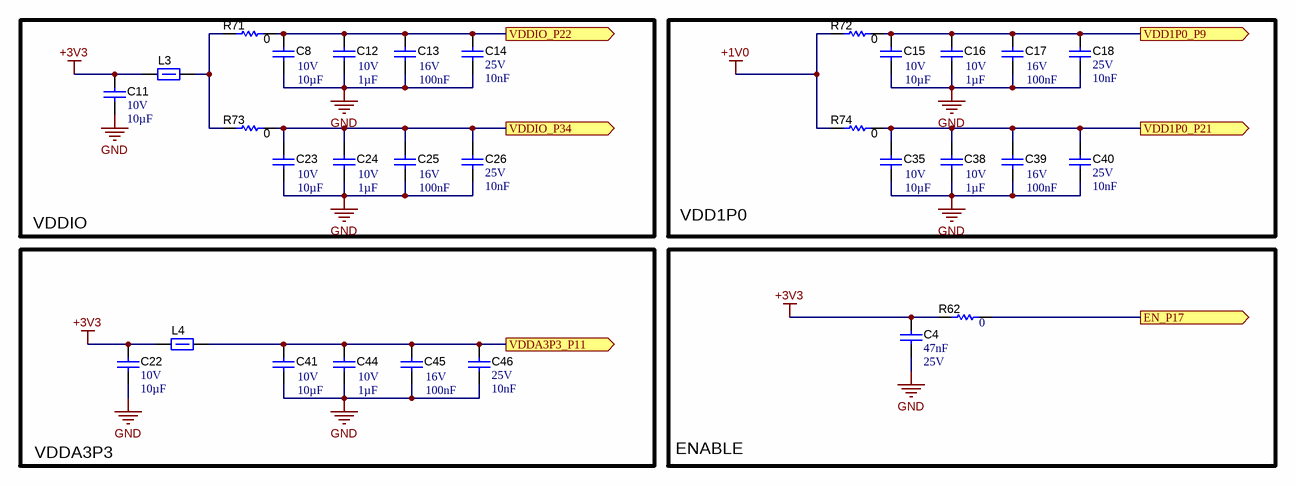
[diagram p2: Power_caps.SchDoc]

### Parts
C4  Cap_F: 47nF  VDC_V: 25V  [0402]  (hidden comment: GRM155R71E473KA88D)
C8  VDC_V: 10V  Cap_F: 10µF  [0402S]  (hidden comment: GRM155R61A106ME11D)
C11  VDC_V: 10V  Cap_F: 10µF  [0402S]  (hidden comment: GRM155R61A106ME11D)
C12  Cap_F: 1µF  VDC_V: 10V  [0402S]  (hidden comment: GRT155C71A105KE13D)
C13  Cap_F: 100nF  VDC_V: 16V  [0402S]  (hidden comment: C0402C104K4RACAUTO)
C14  VDC_V: 25V  Cap_F: 10nF  [0402S]  (hidden comment: GRM155R71E103KA01D)
C15  VDC_V: 10V  Cap_F: 10µF  [0402S]  (hidden comment: GRM155R61A106ME11D)
C16  Cap_F: 1µF  VDC_V: 10V  [0402S]  (hidden comment: GRT155C71A105KE13D)
C17  Cap_F: 100nF  VDC_V: 16V  [0402S]  (hidden comment: C0402C104K4RACAUTO)
C18  VDC_V: 25V  Cap_F: 10nF  [0402S]  (hidden comment: GRM155R71E103KA01D)
C22  VDC_V: 10V  Cap_F: 10µF  [0402S]  (hidden comment: GRM155R61A106ME11D)
C23  VDC_V: 10V  Cap_F: 10µF  [0402S]  (hidden comment: GRM155R61A106ME11D)
C24  Cap_F: 1µF  VDC_V: 10V  [0402S]  (hidden comment: GRT155C71A105KE13D)
C25  Cap_F: 100nF  VDC_V: 16V  [0402S]  (hidden comment: C0402C104K4RACAUTO)
C26  VDC_V: 25V  Cap_F: 10nF  [0402S]  (hidden comment: GRM155R71E103KA01D)
C35  VDC_V: 10V  Cap_F: 10µF  [0402S]  (hidden comment: GRM155R61A106ME11D)
C38  Cap_F: 1µF  VDC_V: 10V  [0402S]  (hidden comment: GRT155C71A105KE13D)
C39  Cap_F: 100nF  VDC_V: 16V  [0402S]  (hidden comment: C0402C104K4RACAUTO)
C40  VDC_V: 25V  Cap_F: 10nF  [0402S]  (hidden comment: GRM155R71E103KA01D)
C41  VDC_V: 10V  Cap_F: 10µF  [0402S]  (hidden comment: GRM155R61A106ME11D)
C44  Cap_F: 1µF  VDC_V: 10V  [0402S]  (hidden comment: GRT155C71A105KE13D)
C45  Cap_F: 100nF  VDC_V: 16V  [0402S]  (hidden comment: C0402C104K4RACAUTO)
C46  VDC_V: 25V  Cap_F: 10nF  [0402S]  (hidden comment: GRM155R71E103KA01D)
L3  BLM18AG102SN1D  [0603]  (value not drawn)
L4  BLM18AG102SN1D  [0603]  (value not drawn)
R62  ValueDisplayed: 0  [0402]  (hidden comment: CRCW04020000Z0EDHP)
R71  ValueDisplayed: 0  [0603]  (hidden comment: RMCF0603ZT0R00)
R72  ValueDisplayed: 0  [0603]  (hidden comment: RMCF0603ZT0R00)
R73  ValueDisplayed: 0  [0603]  (hidden comment: RMCF0603ZT0R00)
R74  ValueDisplayed: 0  [0603]  (hidden comment: RMCF0603ZT0R00)

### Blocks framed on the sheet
VDDIO: C8 C11-C14 C23-C26 L3 R71 R73
VDD1P0: C15-C18 C35 C38-C40 R72 R74
VDDA3P3: C22 C41 C44-C46 L4
ENABLE: C4 R62

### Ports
EN_P17 (out), VDD1P0_P9 (out), VDD1P0_P21 (out), VDDA3P3_P11 (out), VDDIO_P22 (out), VDDIO_P34 (out)

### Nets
+1V0: R72.1 R74.1
+3V3: C4.1 C11.1 C22.1 L3.1 L4.1 R62.1
GND: C4.2 C8.2 C11.2 C12.2 C13.2 C14.1 C15.2 C16.2 C17.2 C18.1 C22.2 C23.2 C24.2 C25.2 C26.1 C35.2 C38.2 C39.2 C40.1 C41.2 C44.2 C45.2 C46.1
EN_P17: R62.2 ; port EN_P17
VDD1P0_P9: C15.1 C16.1 C17.1 C18.2 R72.2 ; port VDD1P0_P9
VDD1P0_P21: C35.1 C38.1 C39.1 C40.2 R74.2 ; port VDD1P0_P21
VDDA3P3_P11: C41.1 C44.1 C45.1 C46.2 L4.2 ; port VDDA3P3_P11
VDDIO_P22: C8.1 C12.1 C13.1 C14.2 R71.2 ; port VDDIO_P22
VDDIO_P34: C23.1 C24.1 C25.1 C26.2 R73.2 ; port VDDIO_P34
NetL3_2: L3.2 R71.1 R73.1

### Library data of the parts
C4 = CMP-0006669-2: CAP, CERM, 0.047 uF, 25 V, +/- 10%, X7R, 0402; Manufacturer: MuRata; TaMin_C: -55°C; Polarized: N; SizeAreaWB_mm2: 3; Value1: Unknown; U/M: EA; TaMax_C: 125°C; SizeZ_mm: 0.6; SizeX_mm: 1; SizeY_mm: 0.5; AEC Category: Q200
C8 C11 C15 C22 C23 C35 C41 = CMP-0006564-3: as C2 on sheet PHY
C12 C16 C24 C38 C44 = CMP-0085818-1: as C3 on sheet PHY
C13 C17 C25 C39 C45 = CMP-0006237-2: as C37 on sheet PHY
C14 C18 C26 C40 C46 = CMP-0006658-2: as C43 on sheet PHY
L3 L4 = CMP-0003343-1: Ferrite Bead, 1000 ohm @ 100 MHz, 0.4 A, 0603; Manufacturer: MuRata; ZTyp@100MHz_Ohm: 1k; SizeAreaWB_mm2: 4.68; DCR_ohm: 0.5; Value1: 0.5 ohm; Imax_A: 400mA; SizeZ_mm: 1; SizeX_mm: 1.6; SizeY_mm: 0.8; Value2: 0.4A; SizeArea_mm2: 1.28
R62 = CMP-0081856-1: as R99 on sheet PHY
R71-R74 = CMP-0023343-3: as R15 on sheet Main

## Sheet PHY_LED.SchDoc
size A4; Date: Not shown in title block; ApprovedBy: Not shown in title block; CheckedBy: Not shown in title block; Author: Not shown in title block; CompanyName: Not shown in title block; Engineer: Not shown in title block; Organization: Not shown in title block; Address1: Not shown in title block; Address2: Not shown in title block; Address3: Not shown in title block; Address4: Not shown in title block; DocumentNumber: 8; Revision: Use project parameter SCH_Rev; SheetNumber: 8; SheetTotal: 19; PageSetup: Record=PageOptions¦CenterHorizontal=True¦CenterVertical=True¦PrintScale=0.93¦XCorrection=1.00¦YCorrection=1.00¦PrintKind=0¦BorderSize=5000000¦LeftOffset=0¦BottomOffset=0¦Orientation=2¦PaperLength=1000¦PaperWidth=1000¦Scale=100¦PaperSource=15¦PrintQuality=600¦MediaType=1¦DitherType=10¦PaperKind=Letter¦PrintScaleMode=1
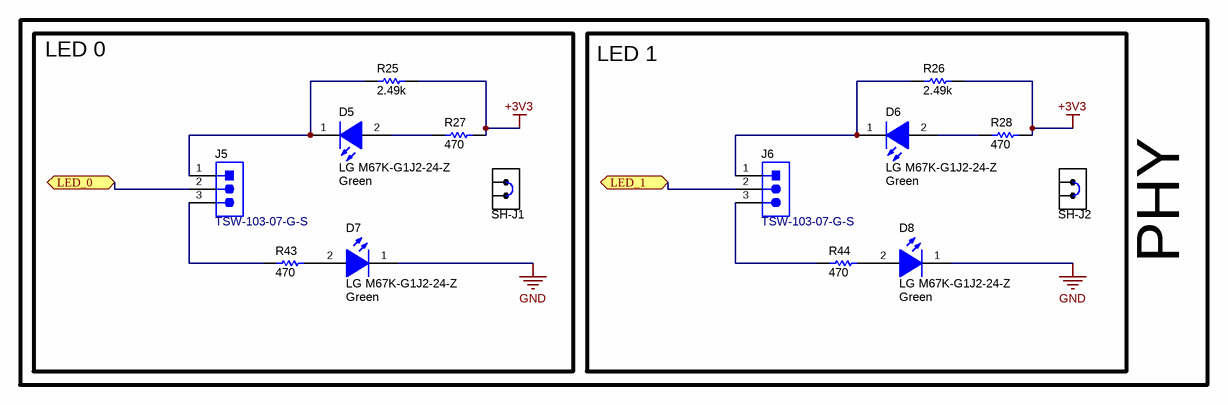
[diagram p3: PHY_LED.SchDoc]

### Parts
D5  LG M67K-G1J2-24-Z  value Green  [LG_M67K_Green]
D6  LG M67K-G1J2-24-Z  value Green  [LG_M67K_Green]
D7  LG M67K-G1J2-24-Z  value Green  [LG_M67K_Green]
D8  LG M67K-G1J2-24-Z  value Green  [LG_M67K_Green]
J5  TSW-103-07-G-S  [TSW-103-07-X-S]
J6  TSW-103-07-G-S  [TSW-103-07-X-S]
R25  ValueDisplayed: 2.49k  [0402]  (hidden comment: CRCW04022K49FKED)
R26  ValueDisplayed: 2.49k  [0402]  (hidden comment: CRCW04022K49FKED)
R27  ValueDisplayed: 470  [0402]  (hidden comment: CRCW0402470RJNED)
R28  ValueDisplayed: 470  [0402]  (hidden comment: CRCW0402470RJNED)
R43  ValueDisplayed: 470  [0402]  (hidden comment: CRCW0402470RJNED)
R44  ValueDisplayed: 470  [0402]  (hidden comment: CRCW0402470RJNED)
SH-J1  SPC02SYAN  [SPC02SYAN]  (value not drawn)
SH-J2  SPC02SYAN  [SPC02SYAN]  (value not drawn)

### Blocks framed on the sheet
LED 0: D5 D7 J5 R25 R27 R43 SH-J1
LED 1: D6 D8 J6 R26 R28 R44 SH-J2

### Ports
LED_0 (bidir), LED_1 (bidir)

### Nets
+3V3: R25.2 R26.2 R27.2 R28.2
GND: D7.1(K) D8.1(K)
AE_LED_0: J5.2 ; port LED_0
AE_LED_1: J6.2 ; port LED_1
NetD5_1: D5.1(K) J5.1 R25.1
NetD5_2: D5.2(A) R27.1
NetD6_1: D6.1(K) J6.1 R26.1
NetD6_2: D6.2(A) R28.1
NetD7_2: D7.2(A) R43.2
NetD8_2: D8.2(A) R44.2
NetJ5_3: J5.3 R43.1
NetJ6_3: J6.3 R44.1

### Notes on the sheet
- PHY

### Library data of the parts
D5-D8 = CMP-0002971-3: LED, Green, SMD; Manufacturer: OSRAM; Value2: 1.8V; Type: AlInGaP; Io_A: 2mA; Tjmax_C: 125°C; Value1: W; Vr_V: 12V; Angle: 120
J5 J6 = CMP-0075407-1: as J16 on sheet PHY
R25 R26 = CMP-0026237-1: RES, 2.49 k, 1%, 0.063 W, 0402; Manufacturer: Vishay-Dale; Power_W: 63mW; TempCo: 100 ppm/C; Value_Code: 2k49; U/M: EA; Value: 2.49k; EIA_Code: E96; SizeX_mm: 1; SizeY_mm: 0.5; SizeZ_mm: 0.6; Value2: 0.063W; VDC_V: 50V; AEC Category: Q200
R27 R28 R43 R44 = CMP-0026934-1: RES, 470, 5%, 0.063 W, 0402; Manufacturer: Vishay-Dale; Power_W: 63mW; TempCo: 200 ppm/C; Value_Code: 470R; U/M: EA; Value: 470; EIA_Code: E24; SizeX_mm: 1; SizeY_mm: 0.5; SizeZ_mm: 0.6; Value2: 0.063W; VDC_V: 50V; AEC Category: Q200
SH-J1 SH-J2 = CMP-0003642-1: as SH-J5 on sheet Main

## Sheet MDI.SchDoc
size A4; Date: Not shown in title block; ApprovedBy: Not shown in title block; CheckedBy: Not shown in title block; Author: Not shown in title block; CompanyName: Not shown in title block; Engineer: Not shown in title block; Organization: Not shown in title block; Address1: Not shown in title block; Address2: Not shown in title block; Address3: Not shown in title block; Address4: Not shown in title block; DocumentNumber: 9; Revision: Use project parameter SCH_Rev; SheetNumber: 9; SheetTotal: 19; PageSetup: Record=PageOptions¦CenterHorizontal=True¦CenterVertical=True¦PrintScale=0.93¦XCorrection=1.00¦YCorrection=1.00¦PrintKind=0¦BorderSize=5000000¦LeftOffset=0¦BottomOffset=0¦Orientation=2¦PaperLength=1000¦PaperWidth=1000¦Scale=100¦PaperSource=15¦PrintQuality=600¦MediaType=1¦DitherType=10¦PaperKind=Letter¦PrintScaleMode=1
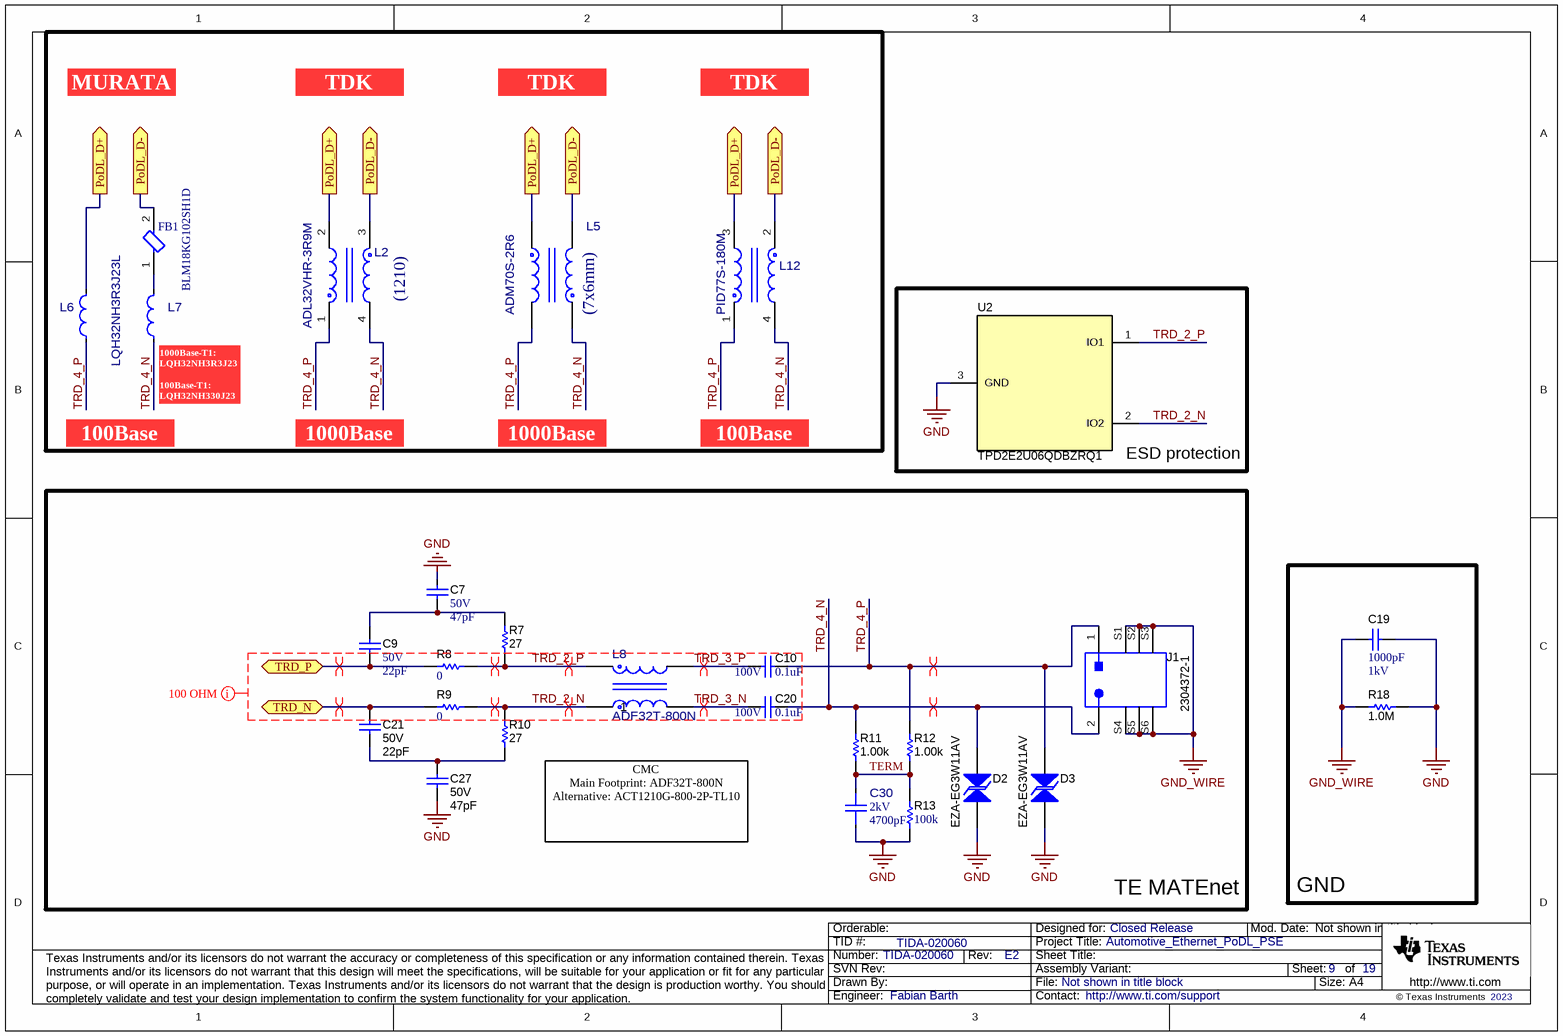
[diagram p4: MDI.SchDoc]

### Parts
C7  VDC_V: 50V  ValueDisplayed: 47pF  [0402S]  (hidden comment: GRM1555C1H470FA01D)
C9  VDC_V: 50V  ValueDisplayed: 22pF  [0402S]  (hidden comment: GRM1555C1H220FA01D)
C10  VDC_V: 100V  ValueDisplayed: 0.1uF  [0603]  (hidden comment: CGA3E3X7S2A104K080AB)
C19  ValueDisplayed: 1000pF  VDC_V: 1kV  [1206]  (hidden comment: GRM31BR73A102KW01L)
C20  VDC_V: 100V  ValueDisplayed: 0.1uF  [0603]  (hidden comment: CGA3E3X7S2A104K080AB)
C21  VDC_V: 50V  ValueDisplayed: 22pF  [0402S]  (hidden comment: GRM1555C1H220FA01D)
C27  VDC_V: 50V  ValueDisplayed: 47pF  [0402S]  (hidden comment: GRM1555C1H470FA01D)
C30  VDC_V: 2kV  ValueDisplayed: 4700pF  [FP-C1210C472KGRAC7800_1210-MFG]  (hidden comment: C1210C472KGRAC7800)
D2  EZA-EG3W11AV  [0603]
D3  EZA-EG3W11AV  [0603]
FB1  BLM18KG102SH1D  [FP-BLM18-0_15-t0_8-IPC_C]
J1  2304372-1  [TE_1PORT_B1-B]
L2  ADL32VHR-3R9M  [FP-ADL32VHR-3R9M_SMT_3MM2_2MM5-MFG]
L5  ADM70S-2R6  [FP-ADM70S-2R6_SMT_7MM0_6MM0-MFG]
L6  LQH32NH3R3J23L  [FP-LQH32NH3R3J23L_1210.0-MFG]  (value not drawn)
L7  LQH32NH3R3J23L  [FP-LQH32NH3R3J23L_1210.0-MFG]
L8  ADF32T-800N  [FP-ADF32T-800N_SMT_CMC_3MM2_2MM5-MFG]
L12  PID77S-180M  [FP-PID77S-180M_SMT4_7MM5_7MM5-MFG]
R7  ValueDisplayed: 27  [0402S]  (hidden comment: CRCW040227R0JNED)
R8  ValueDisplayed: 0  [0402S]  (hidden comment: CRCW04020000Z0EDHP)
R9  ValueDisplayed: 0  [0402S]  (hidden comment: CRCW04020000Z0EDHP)
R10  ValueDisplayed: 27  [0402S]  (hidden comment: CRCW040227R0JNED)
R11  ValueDisplayed: 1.00k  [0805_HV]  (hidden comment: CRCW08051K00FKEA)
R12  ValueDisplayed: 1.00k  [0805_HV]  (hidden comment: CRCW08051K00FKEA)
R13  ValueDisplayed: 100k  [1206]  (hidden comment: ERJ-8ENF1003V)
R18  ValueDisplayed: 1.0M  [1206]  (hidden comment: CRCW12061M00JNEA)
U2  TPD2E2U06QDBZRQ1  [DBZ0003A_N]

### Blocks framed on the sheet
ESD protection: U2
TE MATEnet: C7 C9 C10 C20 C21 C27 C30 D2 D3 J1 L8 R7-R13
GND: C19 R18

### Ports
PoDL_D+ (out), PoDL_D- (out), TRD_N (bidir), TRD_P (bidir)

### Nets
GND: C7.1 C19.1 C27.2 C30.1 D2.2 D3.2 R13.1 R18.2 U2.3(GND)
GND_WIRE: C19.2 J1.S1(GND) J1.S2(GND) J1.S3(GND) J1.S4(GND) J1.S5(GND) J1.S6(GND) R18.1
PoDL_D+: L2.2 L5.3 L6.2 L12.3 ; port PoDL_D+
PoDL_D-: FB1.2 L2.3 L5.4 L12.2 ; port PoDL_D-
TERM: C30.2 R11.1 R12.1 R13.2
TRD_2_N: L8.1 R9.2 R10.2 U2.2(IO2)
TRD_2_P: L8.2 R7.1 R8.2 U2.1(IO1)
TRD_3_N: C20.2 L8.4
TRD_3_P: C10.2 L8.3
TRD_4_N: C20.1 D2.1 J1.2 L2.4 L5.1 L7.1 L12.4 R11.2
TRD_4_P: C10.1 D3.1 J1.1 L2.1 L5.2 L6.1 L12.1 R12.2
TRD_N: C21.1 R9.1 ; port TRD_N
TRD_P: C9.2 R8.1 ; port TRD_P
NetC7_2: C7.2 C9.1 R7.2
NetC21_2: C21.2 C27.1 R10.1
NetFB1_1: FB1.1 L7.2

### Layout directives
differential pair: TRD_2_N, TRD_2_P, TRD_3_N, TRD_3_P, TRD_4_N, TRD_4_P, TRD_N, TRD_P
net class 100 OHM: TRD_2_N, TRD_2_P, TRD_3_N, TRD_3_P

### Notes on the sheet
- MURATA
- TDK
- (near L2) (1210)
- (near L5) (7x6mm)
- 100Base
- (near L7) 1000Base-T1: LQH32NH3R3J23
  100Base-T1: LQH32NH330J23
- 1000Base
- CMC
  Main Footprint: ADF32T-800N
  Alternative: ACT1210G-800-2P-TL10

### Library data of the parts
C7 = CMP-0006467-2: CAP, CERM, 47 pF, 50 V, +/- 1%, C0G/NP0, 0402; Manufacturer: MuRata; TaMin_C: -55°C; Polarized: N; SizeAreaWB_mm2: 3; Value1: Unknown; U/M: EA; Value: 47pF; TaMax_C: 125°C; SizeZ_mm: 0.6; SizeX_mm: 1; SizeY_mm: 0.5; Cap_Case: 0402; AEC Category: Q200
C9 = CMP-0006438-2: CAP, CERM, 22 pF, 50 V, +/- 1%, C0G/NP0, 0402; Manufacturer: MuRata; TaMin_C: -55°C; Polarized: N; SizeAreaWB_mm2: 3; Value1: Unknown; U/M: EA; Value: 22pF; TaMax_C: 125°C; SizeZ_mm: 0.6; SizeX_mm: 1; SizeY_mm: 0.5; Cap_Case: 0402; AEC Category: Q200
C10 C20 = CMP-0007099-4: CAP, CERM, 0.1 uF, 100 V, +/- 10%, X7S, AEC-Q200 Grade 1, 0603; Manufacturer: TDK; TaMin_C: -55°C; Polarized: N; SizeAreaWB_mm2: 4.68; Value1: 0.04959 ohm; U/M: EA; Value: 0.1uF; TaMax_C: 125°C; SizeZ_mm: 1; SizeX_mm: 1.6; SizeY_mm: 0.8; SizeArea_mm2: 1.28; AEC Qualified: Y; Cap_F: 100nF; AEC Category: Q200; ESR_ohm: 49.59m; IRMS_A: 751.618mA
C19 = CMP-0008916-2: CAP, CERM, 1000 pF, 1000 V, +/- 10%, X7R, 1206; Manufacturer: MuRata; SizeZ_mm: 1.35; SizeArea_mm2: 5.12; AEC Category: Q200; Cap_F: 1nF; U/M: EA; SizeY_mm: 1.6; Value1: Unknown; SizeX_mm: 3.2; Value2: 1000V; TaMax_C: 125°C; Polarized: N; SizeAreaWB_mm2: 10.92; Value: 1000pF; TaMin_C: -55°C
C21 = CMP-0006438-1: CAP, CERM, 22 pF, 50 V, +/- 1%, C0G/NP0, 0402; Manufacturer: MuRata; TaMin_C: -55°C; Polarized: N; SizeAreaWB_mm2: 3; Value1: Unknown; U/M: EA; Value: 22pF; TaMax_C: 125°C; SizeZ_mm: 0.6; SizeX_mm: 1; SizeY_mm: 0.5; Cap_Case: 0402; AEC Category: Q200
C27 = CMP-0006467-1: CAP, CERM, 47 pF, 50 V, +/- 1%, C0G/NP0, 0402; Manufacturer: MuRata; TaMin_C: -55°C; Polarized: N; SizeAreaWB_mm2: 3; Value1: Unknown; U/M: EA; Value: 47pF; TaMax_C: 125°C; SizeZ_mm: 0.6; SizeX_mm: 1; SizeY_mm: 0.5; Cap_Case: 0402; AEC Category: Q200
C30 = CMP-0120005-1: Multilayer Ceramic Capacitor, 4700 pF, 2000 V, ± 10%, X7R, 1210 [3225 Metric]; Manufacturer: KEMET; TempCo: 15%; Value: 4.7nF; SizeZ_mm: 2.3mm; AEC Qualified: No
D2 D3 = CMP-0086344-2: Diode, TVS, Bi, AEC-Q101, 0603; Manufacturer: Panasonic; SizeX_mm: 1.6; AEC Qualified: Y; SizeArea_mm2: 1.28; SizeY_mm: 0.8; SizeAreaWB_mm2: 4.68; AEC Category: Q101; SizeZ_mm: 1
FB1 = CMP-06046-000009-2: Chip Ferrite Bead, 0603, 1000Ω @ 100MHz, 0.2Ω, 25%, 1A; Number of Lines: 1; DC Resistance (DCR): 200mR
J1 = CMP-0054903-2: Header(shrouded), 2x1, R/A, TH; Manufacturer: TE Connectivity; Gender: Male; Pitch_mm: 1.8; CT: FALSE; Row_Count: 1; Shrouded: Y
L2 = CMP-0098175-1: Differential Mode Choke 3.9uH 540mA 0.36Ohm 3.2x2.5x2.5mm SMT; Manufacturer: TDK; Ind_H: 3.9µH; Isat: 860mA; DCR_ohm: 0.36; Tolerance_%: 20%; SizeZ_mm: 2.5mm; Test Frequency: 100kHz; AEC Qualified: No
L5 = CMP-0098176-1: Differential Mode Choke 2.6uH 1.5A 84mOhm 7.0x6.0x3.5mm SMT; Manufacturer: TDK; Tolerance_%: 20%; SizeZ_mm: 3.5mm; Self Resonant Frequency: 20MHz; Ind_H: 2.6µH; Isat: 2.2A; Test Frequency: 100kHz; AEC Qualified: No; DCR_ohm: 84m
L6 L7 = CMP-0121122-1: Wire Wound Ferrite Inductor for Automotive 3.3μH ±5% 0.24Ω 425mA 1210; Manufacturer: Murata; AEC Grade: Grade 1; AEC Qualified: Yes; DCR_ohm: 0.24; SizeZ_mm: 2.2mm; Value: 3.3uH; Self Resonant Frequency: 65MHz; Test Frequency: 1MHz; Tolerance_%: 0.05%
L8 = CMP-0098174-1: Common Mode Choke for Ethernet 1000BASE-T1; Manufacturer: TDK; Ind_H: 80µH; Imax_A: 100mA; AEC Qualified: No; Shrouded: true; Test Frequency: 100kHz; Material: Ferrite; Tolerance_%: 30%; SizeZ_mm: 2.5mm; DCR_ohm: 3
L12 = CMP-0001515-1: Differential Mode Choke 18uH 1.8A 0.103 Ohm 7.5x7.5x7.5mm SMT; Manufacturer: TDK; DCR_ohm: 0.103; Ind_H: 18µH; SizeZ_mm: 7.5mm; AEC Qualified: No; Imax_A: 1800mA; Isat: 2200mA; Test Frequency: 100kHz; Tolerance_%: 20%
R7 R10 = CMP-0026888-2: RES, 27, 5%, 0.063 W, 0402; Manufacturer: Vishay-Dale; Power_W: 63mW; TempCo: 200 ppm/C; Value_Code: 27R0; U/M: EA; Value: 27; EIA_Code: E24; SizeX_mm: 1; SizeY_mm: 0.5; SizeZ_mm: 0.6; Value2: 0.063W; VDC_V: 50V; AEC Category: Q200
R8 R9 = CMP-0081856-1: as R99 on sheet PHY
R11 R12 = CMP-0020951-1: RES, 1.00 k, 1%, 0.125 W, 0805; Manufacturer: Vishay-Dale; Power_W: 125mW; TempCo: 100 ppm/C; Value_Code: 1k00; U/M: EA; Value: 1.00k; EIA_Code: E96; Res_ohm: 1k; SizeX_mm: 2; SizeY_mm: 1.25; SizeZ_mm: 1.45; Value2: 0.125W; SizeArea_mm2: 2.5; VDC_V: 150V; AEC Category: Q200
R13 = CMP-0017285-3: RES, 100 k, 1%, 0.25 W, AEC-Q200 Grade 0, 1206; Manufacturer: Panasonic; Power_W: 250mW; TempCo: 100 ppm/C; Value: 100k; EIA_Code: E96; SizeX_mm: 3.2; SizeY_mm: 1.6; SizeZ_mm: 1.35; Value2: 0.25W; SizeArea_mm2: 5.12; AEC Qualified: Y; VDC_V: 200V; AEC Category: Q200; AEC Grade: 0; SizeAreaWB_mm2: 10.92
R18 = CMP-0018610-3: RES, 1.0 M, 5%, 0.25 W, AEC-Q200 Grade 0, 1206; Manufacturer: Vishay-Dale; Power_W: 250mW; TempCo: 200 ppm/C; Value_Code: 1M00; Value: 1.0Meg; EIA_Code: E24; Res_ohm: 1M; SizeX_mm: 3.2; SizeY_mm: 1.6; SizeZ_mm: 1.35; Value2: 0.25W; SizeArea_mm2: 5.12; AEC Qualified: Y; VDC_V: 200V; AEC Category: Q200; AEC Grade: 0
U2 = CMP-0073594-1: Automotive Dual-Channel High-Speed ESD Protection Device, DBZ0003A (SOT-23-3); Alternate Manufacturer: Texas Instruments; SizeAreaWB_mm2: 14.0; U/M: EA; SizeZ_mm: 1.12; SizeX_mm: 2.5; SizeY_mm: 3.0; SizeArea_mm2: 7.5; CompType: IC

## Sheet Hardware.SchDoc
size A4; Date: Not shown in title block; ApprovedBy: Not shown in title block; CheckedBy: Not shown in title block; Author: Not shown in title block; CompanyName: Not shown in title block; Engineer: Not shown in title block; Organization: Not shown in title block; Address1: Not shown in title block; Address2: Not shown in title block; Address3: Not shown in title block; Address4: Not shown in title block; DocumentNumber: 5; Revision: Use project parameter SCH_Rev; SheetNumber: 5; SheetTotal: 19; PageSetup: Record=PageOptions¦CenterHorizontal=True¦CenterVertical=True¦PrintScale=0.93¦XCorrection=1.00¦YCorrection=1.00¦PrintKind=0¦BorderSize=5000000¦LeftOffset=0¦BottomOffset=0¦Orientation=2¦PaperLength=1000¦PaperWidth=1000¦Scale=100¦PaperSource=15¦PrintQuality=600¦MediaType=1¦DitherType=10¦PaperKind=Letter¦PrintScaleMode=1
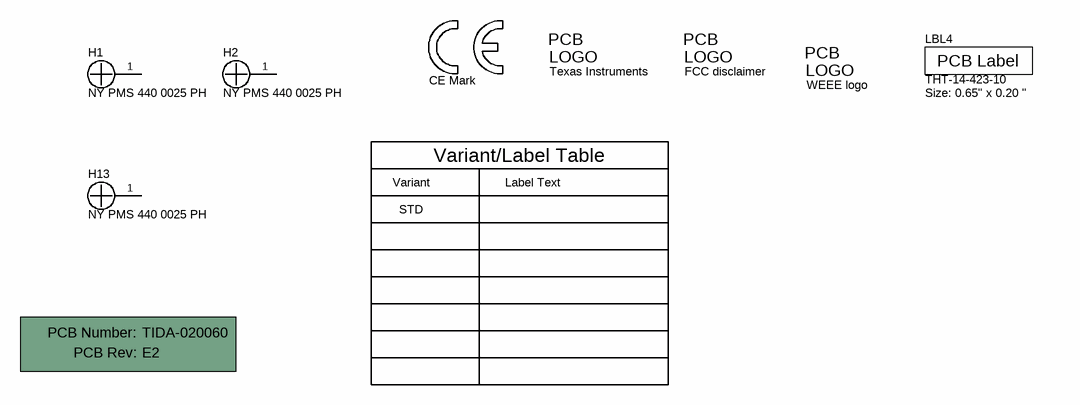
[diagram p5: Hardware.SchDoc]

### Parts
!PCB1  Printed Circuit Board  (value not drawn)  (mechanical)
H1  NY PMS 440 0025 PH  [NY PMS 440 0025 PH]
H2  NY PMS 440 0025 PH  [NY PMS 440 0025 PH]
H13  NY PMS 440 0025 PH  [NY PMS 440 0025 PH]
LBL4  THT-14-423-10  Note: Size: 0.65" x 0.20 "  [Label_650x200]
Logo8  WEEE logo  [WEEE_Minimum]  (no BOM)
Logo9  CE Mark  [CE_Mark_5mm]  (no BOM)
Logo10  Texas Instruments  [TI_Stacked_Overlay_Small]  (no BOM)
Logo11  FCC disclaimer  [FCC_disclaimer]  (no BOM)

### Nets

Not connected (* = marked no-connect by the designer): H1 1; H2 1; H13 1

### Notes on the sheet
- Variant
- Variant/Label Table
- Label Text
- STD

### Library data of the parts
!PCB1 = CMP-0003618-2: Manufacturer: Any; PartNumber: TIDA-020060
H1 H2 H13 = CMP-0003617-1: Machine Screw, Round, #4-40 x 1/4, Nylon, Philips panhead; Manufacturer: B&F Fastener Supply; CompType: Hardware
LBL4 = CMP-0003625-1: Thermal Transfer Printable Labels, 0.650" W x 0.200" H - 10,000 per roll; Manufacturer: Brady; CompType: Label
Logo8 = CMP-0074769-3: Manufacturer: Texas Instruments; AEC Category: Q200; CompType: IC
Logo9 = CMP-0074844-1: SymbolCreator: a0412235
Logo10 = CMP-0074838-1: Texas Instrument Corporate Signature; SymbolCreator: a0412235; Lib Reference: TI_Logo; Library Reference: Logo
Logo11 = CMP-0074847-1: FCC_disclaimer; Library Reference: Logo

## Sheet 100Pin.SchDoc
size A4; Date: Not shown in title block; ApprovedBy: Not shown in title block; CheckedBy: Not shown in title block; Author: Not shown in title block; CompanyName: Not shown in title block; Engineer: Not shown in title block; Organization: Not shown in title block; Address1: Not shown in title block; Address2: Not shown in title block; Address3: Not shown in title block; Address4: Not shown in title block; DocumentNumber: 2; Revision: Use project parameter SCH_Rev; SheetNumber: 2; SheetTotal: 19; PageSetup: Record=PageOptions¦CenterHorizontal=True¦CenterVertical=True¦PrintScale=0.93¦XCorrection=1.00¦YCorrection=1.00¦PrintKind=0¦BorderSize=5000000¦LeftOffset=0¦BottomOffset=0¦Orientation=2¦PaperLength=1000¦PaperWidth=1000¦Scale=100¦PaperSource=15¦PrintQuality=600¦MediaType=1¦DitherType=10¦PaperKind=Letter¦PrintScaleMode=1
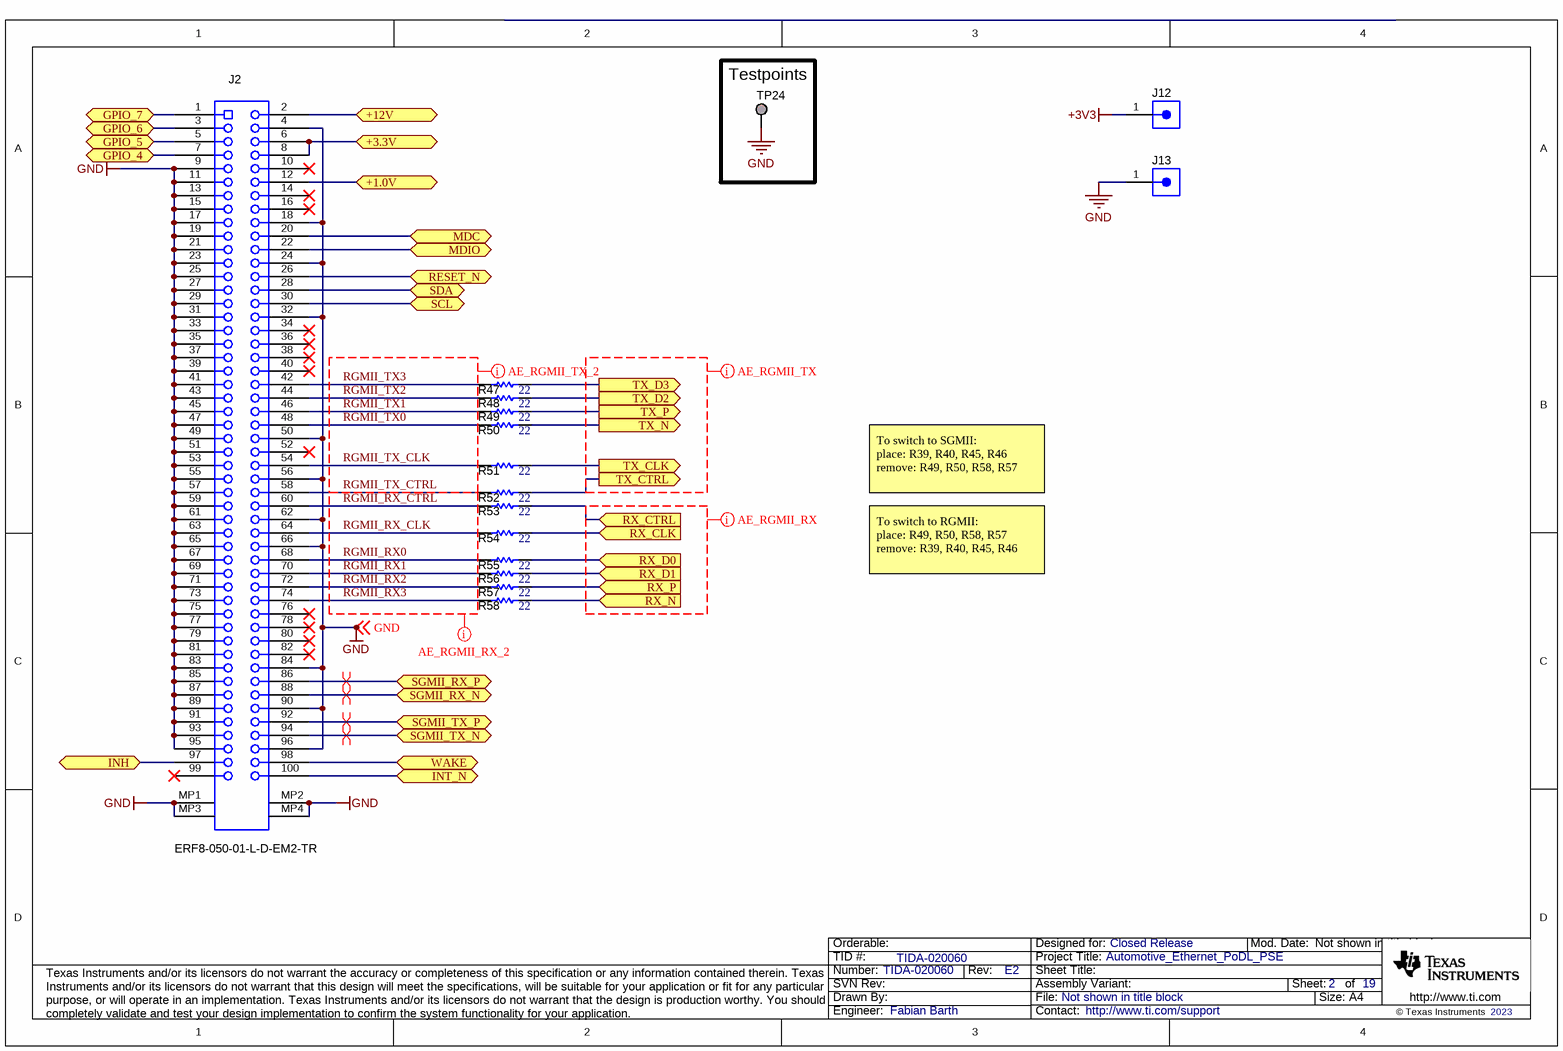
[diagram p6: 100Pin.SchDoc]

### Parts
J2  ERF8-050-01-L-D-EM2-TR  [Samtec_ERF8-050-01-x-D-EM2]
J12  61300111121  [WURTH_61300111121]  (value not drawn)
J13  61300111121  [WURTH_61300111121]  (value not drawn)
R47  ValueDisplayed: 22  [0402S]  (hidden comment: ERJ-2GEJ220X)
R48  ValueDisplayed: 22  [0402S]  (hidden comment: ERJ-2GEJ220X)
R49  ValueDisplayed: 22  [0402S]  (hidden comment: ERJ-2GEJ220X)
R50  ValueDisplayed: 22  [0402S]  (hidden comment: ERJ-2GEJ220X)
R51  ValueDisplayed: 22  [0402S]  (hidden comment: ERJ-2GEJ220X)
R52  ValueDisplayed: 22  [0402S]  (hidden comment: ERJ-2GEJ220X)
R53  ValueDisplayed: 22  [0402S]  (hidden comment: ERJ-2GEJ220X)
R54  ValueDisplayed: 22  [0402S]  (hidden comment: ERJ-2GEJ220X)
R55  ValueDisplayed: 22  [0402S]  (hidden comment: ERJ-2GEJ220X)
R56  ValueDisplayed: 22  [0402S]  (hidden comment: ERJ-2GEJ220X)
R57  ValueDisplayed: 22  [0402S]  (hidden comment: ERJ-2GEJ220X)
R58  ValueDisplayed: 22  [0402S]  (hidden comment: ERJ-2GEJ220X)
TP24  1502-2  [Keystone1502-2]  (value not drawn)

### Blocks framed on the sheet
Testpoints: TP24

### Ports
+1.0V (bidir), +3.3V (bidir), +12V (bidir), GPIO_4 (bidir), GPIO_5 (bidir), GPIO_6 (bidir), GPIO_7 (bidir), INH (bidir), INT_N (bidir), MDC (bidir), MDIO (bidir), RESET_N (bidir), RX_CLK (in), RX_CTRL (in), RX_D0 (in), RX_D1 (in), RX_N (in), RX_P (in), SCL (bidir), SDA (bidir), SGMII_RX_N (bidir), SGMII_RX_P (bidir), SGMII_TX_N (bidir), SGMII_TX_P (bidir), TX_CLK (out), TX_CTRL (out), TX_D2 (out), TX_D3 (out), TX_N (out), TX_P (out), WAKE (bidir)

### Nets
+3V3: J12.1
GND: J2.4 J2.9 J2.11 J2.13 J2.15 J2.17 J2.18 J2.19 J2.21 J2.23 J2.24 J2.25 J2.27 J2.29 J2.31 J2.32 J2.33 J2.35 J2.37 J2.39 J2.41 J2.43 J2.45 J2.47 J2.49 J2.50 J2.51 J2.53 J2.55 J2.56 J2.57 J2.59 J2.61 J2.62 J2.63 J2.65 J2.66 J2.67 J2.69 J2.71 J2.73 J2.75 J2.77 J2.79 J2.81 J2.83 J2.84 J2.85 J2.87 J2.89 J2.90 J2.91 J2.93 J2.95 J2.96 J2.MP1 J2.MP2 J2.MP3 J2.MP4 J13.1 TP24.1 ; off-sheet GND
+3.3V_conn: J2.6 J2.8 ; port +3.3V
+12V_conn: J2.2 ; port +12V
AE_INH: J2.97 ; port INH
AE_INT_N: J2.100 ; port INT_N
AE_RESET_N: J2.26 ; port RESET_N
AE_RX_CLK: R54.2 ; port RX_CLK
AE_RX_CTRL: R53.2 ; port RX_CTRL
AE_RX_D0: R55.2 ; port RX_D0
AE_RX_D1: R56.2 ; port RX_D1
AE_RX_N: R58.2 ; port RX_N
AE_RX_P: R57.2 ; port RX_P
AE_TX_CLK: R51.2 ; port TX_CLK
AE_TX_CTRL: R52.2 ; port TX_CTRL
AE_TX_D2: R48.2 ; port TX_D2
AE_TX_D3: R47.2 ; port TX_D3
AE_TX_N: R50.2 ; port TX_N
AE_TX_P: R49.2 ; port TX_P
AE_WAKE: J2.98 ; port WAKE
DUT_VDD1P0: J2.12 ; port +1.0V
GPIO_4: J2.7 ; port GPIO_4
GPIO_5: J2.5 ; port GPIO_5
GPIO_6: J2.3 ; port GPIO_6
GPIO_7: J2.1 ; port GPIO_7
MDC: J2.20 ; port MDC
MDIO: J2.22 ; port MDIO
RGMII_RX0: J2.68 R55.1
RGMII_RX1: J2.70 R56.1
RGMII_RX2: J2.72 R57.1
RGMII_RX3: J2.74 R58.1
RGMII_RX_CLK: J2.64 R54.1
RGMII_RX_CTRL: J2.60 R53.1
RGMII_TX0: J2.48 R50.1
RGMII_TX1: J2.46 R49.1
RGMII_TX2: J2.44 R48.1
RGMII_TX3: J2.42 R47.1
RGMII_TX_CLK: J2.54 R51.1
RGMII_TX_CTRL: J2.58 R52.1
SCL: J2.30 ; port SCL
SDA: J2.28 ; port SDA
SGMII_2_RX_N: J2.88 ; port SGMII_RX_N
SGMII_2_RX_P: J2.86 ; port SGMII_RX_P
SGMII_2_TX_N: J2.94 ; port SGMII_TX_N
SGMII_2_TX_P: J2.92 ; port SGMII_TX_P

Not connected (* = marked no-connect by the designer): J2 10* 14* 16* 34* 36* 38* 40* 52* 76* 78* 80* 82* 99*

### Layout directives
differential pair: SGMII_2_RX_N, SGMII_2_RX_P, SGMII_2_TX_N, SGMII_2_TX_P
net class AE_RGMII_RX: (no net found under the mark), RGMII_RX0, RGMII_RX1, RGMII_RX2, RGMII_RX3, RGMII_RX_CLK, RGMII_RX_CTRL, RGMII_TX_CTRL
net class AE_RGMII_TX: (no net found under the mark), RGMII_TX0, RGMII_TX1, RGMII_TX2, RGMII_TX3, RGMII_TX_CLK, RGMII_TX_CTRL

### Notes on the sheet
- To switch to SGMII:
  place: R39, R40, R45, R46
  remove: R49, R50, R58, R57
- To switch to RGMII:
  place: R49, R50, R58, R57
  remove: R39, R40, R45, R46

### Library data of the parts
J2 = CMP-0055719-1: Receptacle, 0.8mm, 50x2, Gold, Edge Mount; Manufacturer: Samtec; CNHeader: FALSE; Current_A: 2.2A; Gender: Female; Voltage_V: 200V; CompType: Card Edge Socket; Row_Count: 2; Pitch_mm: 0.8; CT: TRUE; Cert_UL: Y
J12 J13 = CMP-0054792-1: as J4 on sheet Main
R47-R58 = CMP-0026997-2: RES, 22, 5%, 0.1 W, AEC-Q200 Grade 0, 0402; Manufacturer: Panasonic; Power_W: 100mW; TempCo: 200 ppm/C; Value_Code: 22R0; U/M: EA; Value: 22; SizeX_mm: 1; SizeY_mm: 0.5; SizeZ_mm: 0.6; Value2: 0.1W; AEC Qualified: Y; AEC Grade: 0; AEC Category: Q200; EIA_Code: E24
TP24 = CMP-0055113-1: Terminal, Turret, TH, Double; Manufacturer: Keystone; CT: FALSE; Green_REACh: Passed; CompType: Turret Terminal; Green_Lifecycle: Active

## Sheet 60Pin.SchDoc
size A4; Date: Not shown in title block; ApprovedBy: Not shown in title block; CheckedBy: Not shown in title block; Author: Not shown in title block; CompanyName: Not shown in title block; Engineer: Not shown in title block; Organization: Not shown in title block; Address1: Not shown in title block; Address2: Not shown in title block; Address3: Not shown in title block; Address4: Not shown in title block; DocumentNumber: 3; Revision: Use project parameter SCH_Rev; SheetNumber: 3; SheetTotal: 19; PageSetup: Record=PageOptions¦CenterHorizontal=True¦CenterVertical=True¦PrintScale=0.93¦XCorrection=1.00¦YCorrection=1.00¦PrintKind=0¦BorderSize=5000000¦LeftOffset=0¦BottomOffset=0¦Orientation=2¦PaperLength=1000¦PaperWidth=1000¦Scale=100¦PaperSource=15¦PrintQuality=600¦MediaType=1¦DitherType=10¦PaperKind=Letter¦PrintScaleMode=1
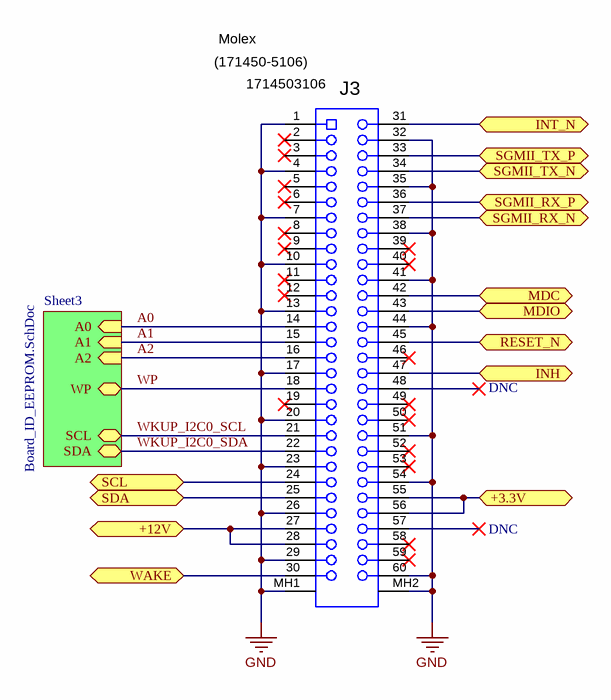
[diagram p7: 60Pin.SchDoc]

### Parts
J3  1714503106  [Molex_1714503106]

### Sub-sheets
Sheet3 = Board_ID_EEPROM.SchDoc: A0 (in), A1 (in), A2 (in), WP (bidir), SCL (bidir), SDA (bidir)

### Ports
+3.3V (bidir), +12V (bidir), INH (bidir), INT_N (bidir), MDC (bidir), MDIO (bidir), RESET_N (bidir), SCL (bidir), SDA (bidir), SGMII_RX_N (bidir), SGMII_RX_P (bidir), SGMII_TX_N (bidir), SGMII_TX_P (bidir), WAKE (bidir)

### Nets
GND: J3.1 J3.4 J3.7 J3.10 J3.13 J3.17 J3.20 J3.23 J3.26 J3.29 J3.32 J3.35 J3.38 J3.41 J3.44 J3.51 J3.54 J3.60 J3.MH1 J3.MH2
+3.3V_conn: J3.55 J3.56 ; port +3.3V
+12V_conn: J3.27 J3.28 ; port +12V
A0: J3.14 ; sheet Sheet3/A0
A1: J3.15 ; sheet Sheet3/A1
A2: J3.16 ; sheet Sheet3/A2
AE_INH: J3.47 ; port INH
AE_INT_N: J3.31 ; port INT_N
AE_RESET_N: J3.45 ; port RESET_N
AE_WAKE: J3.30 ; port WAKE
MDC: J3.42 ; port MDC
MDIO: J3.43 ; port MDIO
SCL: J3.24 ; port SCL
SDA: J3.25 ; port SDA
SGMII_2_RX_N: J3.37 ; port SGMII_RX_N
SGMII_2_RX_P: J3.36 ; port SGMII_RX_P
SGMII_2_TX_N: J3.34 ; port SGMII_TX_N
SGMII_2_TX_P: J3.33 ; port SGMII_TX_P
WKUP_I2C0_SCL: J3.21 ; sheet Sheet3/SCL
WKUP_I2C0_SDA: J3.22 ; sheet Sheet3/SDA
WP: J3.18 ; sheet Sheet3/WP

Not connected (* = marked no-connect by the designer): J3 2* 3* 5* 6* 8* 9* 11* 12* 19* 39* 40* 46* 48* 49* 50* 52* 53* 57* 58* 59*

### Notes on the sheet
- Molex
- (near J3) (171450-5106)
- DNC

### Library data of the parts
J3 = CMP-0086037-1: Receptacle, 0.8mm, 30x2, Gold, SMT; Manufacturer: Molex; Row_Count: 2; Gender: Female; Pitch_mm: 0.8; Current_A: 800mA; Voltage_V: 5V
